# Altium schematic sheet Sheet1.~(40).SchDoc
size A3
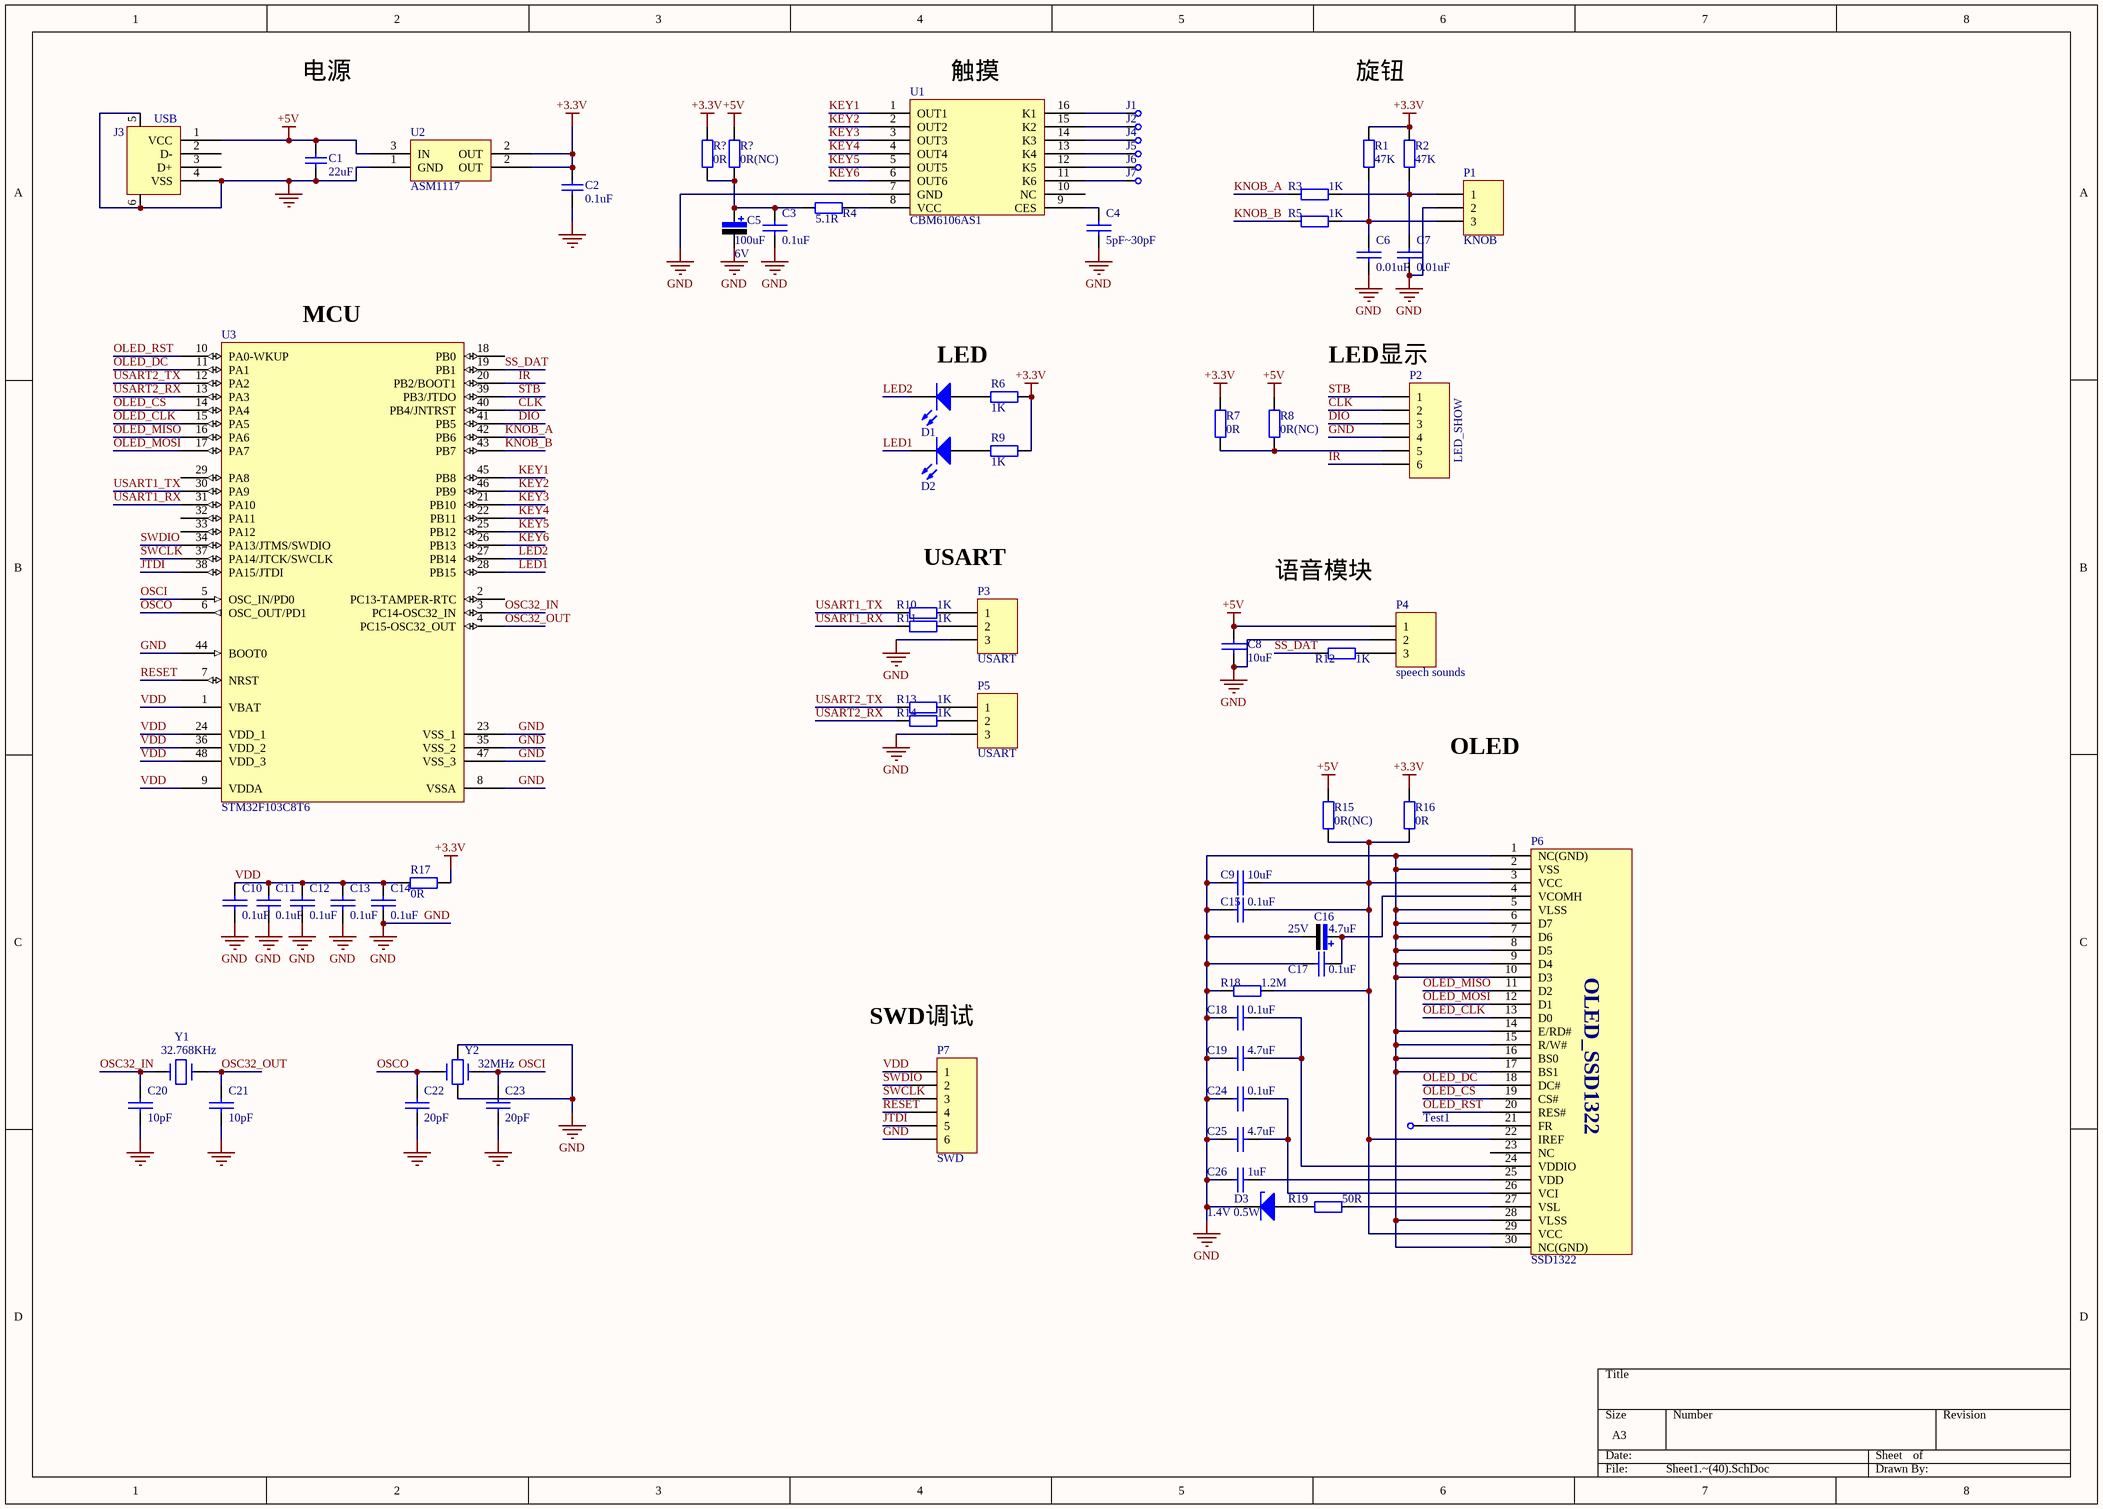
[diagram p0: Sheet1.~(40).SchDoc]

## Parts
(Parts that share a designator on the sheet are numbered #1, #2 ... from top to bottom, then left to right.)
C1  value 22uF  [0402C]  (hidden comment: Cap)
C2  value 0.1uF  [0402C]  (hidden comment: Cap)
C3  0.1uF  [0402C]
C4  5pF~30pF  [0402C]
C5  value 100uF  Vol: 6V  [CAP-3528]  (hidden comment: Cap Pol)
C6  0.01uF  [0402C]
C7  0.01uF  [0402C]
C8  10uF  [0402C]
C9  10uF  [0402C]
C10  0.1uF  [0402C]
C11  0.1uF  [0402C]
C12  0.1uF  [0402C]
C13  0.1uF  [0402C]
C14  0.1uF  [0402C]
C15  0.1uF  [0402C]
C16  value 4.7uF  Vol: 25V  [CAP-3528]  (hidden comment: Cap Pol)
C17  0.1uF  [0402C]
C18  0.1uF  [0402C]
C19  4.7uF  [0402C]
C20  10pF  [0402C]
C21  10pF  [0402C]
C22  20pF  [0402C]
C23  20pF  [0402C]
C24  0.1uF  [0402C]
C25  4.7uF  [0402C]
C26  1uF  [0402C]
D1  LED0  [led0603]  (value not drawn)
D2  LED0  [led0603]  (value not drawn)
D3  value 1.4V 0.5W  [DIODE-1206]  (hidden comment: Diode-Z)
J1  CHECK  [CHECK-A]  (value not drawn)
J2  CHECK  [CHECK-A]  (value not drawn)
J3  USB  [USB_A1]
J4  CHECK  [CHECK-A]  (value not drawn)
J5  CHECK  [CHECK-A]  (value not drawn)
J6  CHECK  [CHECK-A]  (value not drawn)
J7  CHECK  [CHECK-A]  (value not drawn)
P1  KNOB  [HDR3X1_A]
P2  LED_SHOW  [HDR6X1_B2]
P3  USART  [HDR3X1_A]
P4  speech sounds  [HDR3X1_A]
P5  USART  [HDR3X1_A]
P6  SSD1322
P7  SWD  [HDR6X1_B2]
R1  value 47K  [0603-1]  (hidden comment: Res1)
R2  value 47K  [0603-1]  (hidden comment: Res1)
R3  value 1K  [0603-1]  (hidden comment: Res1)
R4  value 5.1R  [0603-1]  (hidden comment: Res1)
R5  value 1K  [0603-1]  (hidden comment: Res1)
R6  value 1K  [0402R]  (hidden comment: Res1)
R7  value 0R  [0402R]  (hidden comment: Res1)
R8  value 0R(NC)  [0402R]  (hidden comment: Res1)
R9  value 1K  [0402R]  (hidden comment: Res1)
R10  value 1K  [0402R]  (hidden comment: Res1)
R11  value 1K  [0402R]  (hidden comment: Res1)
R12  value 1K  [0402R]  (hidden comment: Res1)
R13  value 1K  [0402R]  (hidden comment: Res1)
R14  value 1K  [0402R]  (hidden comment: Res1)
R15  value 0R(NC)  [0402R]  (hidden comment: Res1)
R16  value 0R  [0402R]  (hidden comment: Res1)
R17  value 0R  [0402R]  (hidden comment: Res1)
R18  value 1.2M  [0402R]  (hidden comment: Res1)
R19  value 50R  [0402R]  (hidden comment: Res1)
R?#1  value 0R  [0402R]  (hidden comment: Res1)
R?#2  value 0R(NC)  [0402R]  (hidden comment: Res1)
Test1  CHECK  [CHECK-A]  (value not drawn)
U1  CBM6106AS1
U2  ASM1117  [SOT-223-3]
U3  STM32F103C8T6  [LQFP48_N]
Y1  32.768KHz  [SMD3215]
Y2  32MHz  [Y3225]

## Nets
+3.3V: C2.2 R1.2 R2.2 R6.1 R7.1 R9.1 R16.1 R17.2 R?#1.1 U2.2(OUT)
+5V: C1.2 C8.1 J3.1(VCC) P4.1 R8.1 R15.1 R?#2.1 U2.3(IN)
GND: C1.1 C2.1 C3.2 C4.2 C5.2 C6.2 C7.2 C8.2 C9.2 C10.2 C11.2 C12.2 C13.2 C14.2 C15.2 C16.2 C17.2 C18.2 C19.2 C20.2 C21.2 C22.2 C23.2 C24.2 C25.2 C26.2 D3.2(K) J3.4(VSS) J3.5 J3.6 P1.2 P2.4 P3.3 P4.2 P5.3 P6.1(NC(GND)) P6.2(VSS) P6.5(VLSS) P6.6(D7) P6.7(D6) P6.8(D5) P6.9(D4) P6.10(D3) P6.14(E/RD#) P6.15(R/W#) P6.16(BS0) P6.17(BS1) P6.28(VLSS) P6.30(NC(GND)) P7.6 R18.2 U1.7(GND) U2.1(GND) U3.8(VSSA) U3.23(VSS_1) U3.35(VSS_2) U3.44(BOOT0) U3.47(VSS_3) Y2.2 Y2.4
CLK: P2.2 U3.40(PB4/JNTRST)
DIO: P2.3 U3.41(PB5)
IR: P2.6 U3.20(PB2/BOOT1)
JTDI: P7.5 U3.38(PA15/JTDI)
KEY1: U1.1(OUT1) U3.45(PB8)
KEY2: U1.2(OUT2) U3.46(PB9)
KEY3: U1.3(OUT3) U3.21(PB10)
KEY4: U1.4(OUT4) U3.22(PB11)
KEY5: U1.5(OUT5) U3.25(PB12)
KEY6: U1.6(OUT6) U3.26(PB13)
KNOB_A: R3.1 U3.42(PB6)
KNOB_B: R5.1 U3.43(PB7)
LED1: D2.2(K) U3.28(PB15)
LED2: D1.2(K) U3.27(PB14)
OLED_CLK: P6.13(D0) U3.15(PA5)
OLED_CS: P6.19(CS#) U3.14(PA4)
OLED_DC: P6.18(DC#) U3.11(PA1)
OLED_MISO: P6.11(D2) U3.16(PA6)
OLED_MOSI: P6.12(D1) U3.17(PA7)
OLED_RST: P6.20(RES#) U3.10(PA0-WKUP)
OSC32_IN: C20.1 U3.3(PC14-OSC32_IN) Y1.1
OSC32_OUT: C21.1 U3.4(PC15-OSC32_OUT) Y1.2
OSCI: C23.1 U3.5(OSC_IN/PD0) Y2.3
OSCO: C22.1 U3.6(OSC_OUT/PD1) Y2.1
RESET: P7.4 U3.7(NRST)
SS_DAT: R12.2 U3.19(PB1)
STB: P2.1 U3.39(PB3/JTDO)
SWCLK: P7.3 U3.37(PA14/JTCK/SWCLK)
SWDIO: P7.2 U3.34(PA13/JTMS/SWDIO)
USART1_RX: R11.2 U3.31(PA10)
USART1_TX: R10.2 U3.30(PA9)
USART2_RX: R14.2 U3.13(PA3)
USART2_TX: R13.2 U3.12(PA2)
VDD: C10.1 C11.1 C12.1 C13.1 C14.1 P7.1 R17.1 U3.1(VBAT) U3.9(VDDA) U3.24(VDD_1) U3.36(VDD_2) U3.48(VDD_3)
NetC3_1: C3.1 C5.1 R4.1 R?#1.2 R?#2.2
NetC4_1: C4.1 U1.9(CES)
NetC6_1: C6.1 P1.3 R1.1 R5.2
NetC7_1: C7.1 P1.1 R2.1 R3.2
NetC9_1: C9.1 C15.1 P6.3(VCC) P6.22(IREF) P6.29(VCC) R15.2 R16.2 R18.1
NetC16_1: C16.1 C17.1 P6.4(VCOMH)
NetC18_1: C18.1 C19.1 P6.24(VDDIO)
NetC24_1: C24.1 C25.1 P6.26(VCI)
NetC26_1: C26.1 P6.25(VDD)
NetD1_1: D1.1(A) R6.2
NetD2_1: D2.1(A) R9.2
NetD3_1: D3.1(A) R19.2
NetJ1_1: J1.1 U1.16(K1)
NetJ2_1: J2.1 U1.15(K2)
NetJ4_1: J4.1 U1.14(K3)
NetJ5_1: J5.1 U1.13(K4)
NetJ6_1: J6.1 U1.12(K5)
NetJ7_1: J7.1 U1.11(K6)
NetP2_5: P2.5 R7.2 R8.2
NetP3_1: P3.1 R10.1
NetP3_2: P3.2 R11.1
NetP4_3: P4.3 R12.1
NetP5_1: P5.1 R13.1
NetP5_2: P5.2 R14.1
NetP6_21: P6.21(FR) Test1.1
NetP6_27: P6.27(VSL) R19.1
NetR4_2: R4.2 U1.8(VCC)

Not connected (* = marked no-connect by the designer): J3 2(D-) 3(D+); P6 23(NC); U1 10(NC); U3 2(PC13-TAMPER-RTC) 18(PB0) 29(PA8) 32(PA11) 33(PA12)

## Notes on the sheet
- 电源
- (near U1) 触摸
- 旋钮
- (near U3) MCU
- LED
- (near P2) LED显示
- USART
- 语音模块
- OLED
- (near P7) SWD调试

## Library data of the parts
C1 C2 = Cap: 无极性电容
C3 C4 C6-C15 C17-C26 = CAP: Capacitor
C5 C16 = Cap Pol: 极性电解电容
D1 D2 = LED0: 发光二极管
D3 = Diode-Z: 稳压二极管
J1 J2 J4-J7 Test1 = CHECK: 测试点
J3 = USB: USB接口
P1 P3-P5 = Header 3: 接插件
P2 P7 = Header 6: 接插件
R1-R19 R?#1 R?#2 = Res1: 贴片电阻
U2 = ASM1117: 3.3V稳压芯片
U3 = STM32F103C8T6: STM32 ARM-based 32-bit MCU with 64 Kbytes Flash, 48-pin LQFP, Industrial Temperature
Y1 = CRYSTAL
Y2 = CRYSTAL1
